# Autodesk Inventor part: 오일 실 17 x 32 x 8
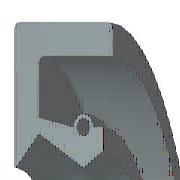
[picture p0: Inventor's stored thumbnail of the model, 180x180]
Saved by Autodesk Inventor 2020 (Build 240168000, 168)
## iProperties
Created: 2012-02
Part Number: 오일 실 17 x 32 x 8
Material: 고무
Description: 샤프트 실 링
Document SubType Name: Modeling
Standard: JIS B 2402
Designer: mdu-01
Standards Organization: JIS
Language: ko-KR
Size Designation: D 17 x 32 x 8
Categories: <MemberInstance><Categories><Category DisplayName="샤프트 부품" InternalName="7f7aeb1f-a693-4053-b835-cee3144e0d98" Mnemonic="SHFT"><Category DisplayName="실링" Intern
Density: 0.93 g/cm^3
Appearance: 고무 - 검은색 - 버전 1.1
IsCustomPart: 1
Author: mdu-01
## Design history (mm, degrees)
revolve "본체" stored, may be unused: angle "d17" = 90 deg
revolve "스프링1" stored, may be unused: angle "d18" = 90 deg
body "Solid1"
sketch "스케치1"
  geometry: L1 (0, 16)-(8, 16); L2 (8, 14.25)-(1.75, 14.25); L3 (1.75, 10.25)-(4.9, 8.5); L4 (4.9, 8.5)-(0, 8.5); L5 (0, 0)-(9.586, 0) reference; L6 (4.9, 8.5)-(6.3, 9.375); L7 (0, 18)-(0, -3) reference; L8 (-1.941, 0)-(11.507, 0) reference; L9 (4.2, 10.6)-(1.75, 11.21); L10 (1.75, 11.21)-(1.75, 14.25); L11 (0, 16)-(0, 8.588); L12 (4.9, 8.5)-(0, 8.5); L13 (1.75, 10.25)-(0.152, 8.528); L14 (8, 16)-(8, 14.25); L15 (5.6, 10.6)-(6.3, 10.6); L16 (6.3, 10.6)-(6.3, 9.375); C1 r 0.455 at (4.9, 10.6); A1 r 0.7 centre (4.9, 10.6) between (5.6, 10.6) and (4.2, 10.6); A2 r 0.088 centre (0.088, 8.588) between (0, 8.588) and (0.152, 8.528); 1 further point
  constraints: 28 end point, 5 horizontal alignment, 5 point on line, 4 point on circle, 4 vertical alignment, 3 centre point, 3 tangent, 2 collinear, 2 horizontal, 2 perpendicular, 1 coincident, 1 parallel
  dimensions: "d0" = 32 diameter of L1 L5 (= SD2); "d1" = 1.75 distance of L1.end L2.start (= SD); "d2" = 0.91 diameter of C1 (= SPDI); "d3" = 1.4 diameter of A1 (= SPDA); "d4" = 17 diameter of L3.end L5 (= NND); "d5" = 20.5 diameter of L3.start L5 (= TKDM); "d7" = 22.42 diameter of L9.end L5 (= TKDM + 0.24 x SWDT); "d8" = 1.75 distance between parallel lines of L11 L10 (= SD); "d9" = 4.9 distance from line of L11 C1.centre (= SPDST); "d10" = 21.2 diameter of C1.centre L5 (= HLDM); "d11" = 0.0875 radius of A2 (= 0.25 x LAB); "d12" = 6.3 distance between parallel lines of L11 L16 (= SDI); "d13" = 18.75 diameter of L6.end L5 (= ABDM); "d14" = 8 distance from line of L11 L1.end (= SWDT)
fillet "모깎기1" dims "d6" = 0.3 (= RR)
other parameters: "SD2" = 32 [user parameter; used in 1 equation term], "SWDT" = 8 [user parameter; used in 2 equation terms], "RR" = 0.3 [user parameter; used in 1 equation term], "SD" = 1.75 [user parameter; used in 2 equation terms], "NND" = 17 [user parameter; used in 1 equation term], "SPDA" = 1.4 [user parameter; used in 1 equation term], "SPDI" = 0.91 [user parameter; used in 1 equation term], "TKDM" = 20.5 [user parameter; used in 2 equation terms], "HLDM" = 21.2 [user parameter; used in 1 equation term], "ABDM" = 18.75 [user parameter; used in 1 equation term], "SDI" = 6.3 [user parameter; used in 1 equation term], "SPDST" = 4.9 [user parameter; used in 1 equation term], "LAB" = 0.35 [user parameter; used in 1 equation term], "d15" = 0, "d16" = 0, "d19" = 0
